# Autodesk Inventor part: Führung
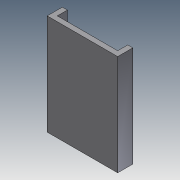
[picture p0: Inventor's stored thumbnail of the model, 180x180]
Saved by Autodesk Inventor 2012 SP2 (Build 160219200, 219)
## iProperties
Created: 2012-10
Part Number: Führung
Material: Standard
Description: =<BEZEICHNUNG DEUTSCH>
Document SubType Name: Modeling
Designer: Massmann
Density: 1 g/cm^3
Author: Massmann
IdentNr: =<SAP MATERIALNUMMER>
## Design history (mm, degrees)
sketch "Skizze1"
  geometry: L1 (-30, -5)-(30, -5); L2 (-30, -5)-(-30, 5); L3 (-30, 5)-(-35, 5); L4 (-35, 5)-(-35, -10); L5 (-35, -10)-(35, -10); L6 (35, -10)-(35, 5); L7 (35, 5)-(30, 5); L8 (30, 5)-(30, -5); 2 further points
  constraints: 16 end point, 4 parallel, 2 collinear, 2 perpendicular, 1 horizontal, 1 midpoint, 1 vertical alignment
  dimensions: "d0" = 60 distance of L1.start L1.end; "d1" = 5 distance between parallel lines of L2 L4; "d2" = 5 distance of L6.end L7.end; "d3" = 5 distance between parallel lines of L5 L1; "d4" = 5 distance from line of point (0, 0) L7; "d5" = 10 distance of L7.end L1.end
extrude "Extrusion1" new body sketch "Skizze1" stored distance "d6" = 100; taper "d7" = 0 deg
node "Volumenkörper1"
node "Volumenkörpern"
node "Oberflächenkörpern"
other parameters: "G_L" = 0.1 [user parameter], "G_B" = 0.1 [user parameter]
